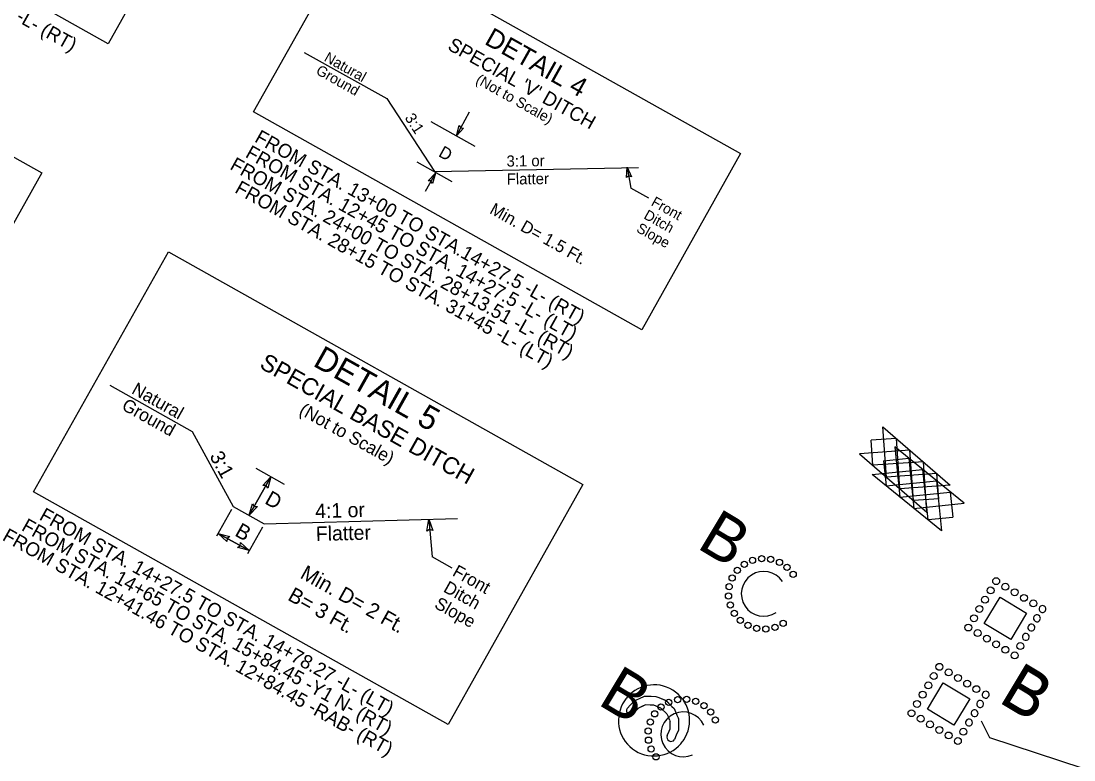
# Model space of a CAD drawing. Extents: x 2283629 to 2286552, y 529718 to 531440.
# Drawn here: x 2284293.2 to 2284634, y 530837.2 to 531076.3 of the extents above; entities that cross this region are included whole.
import ezdxf

# ---------------------------------------------------------------- set-up
doc = ezdxf.new("R2010")
doc.units = 0
for name, color, linetype in [('Draft_Corridor_Graphics_Design', 7, 'Continuous'), ('Draft_RDY_Construction_Class_Element', 7, 'Continuous'), ('P_NCDOT_Terrain_Breakline', 7, 'Continuous'), ('P_NCDOT_Terrain_Hole', 7, 'Continuous'), ('P_NCDOT_Terrain_Island', 7, 'Continuous'), ('P_NCDOT_Terrain_Model_Contour_Major', 7, 'Continuous'), ('P_NCDOT_Terrain_Points_Random', 7, 'Continuous'), ('P_NCDOT_Terrain_Void', 7, 'Continuous'), ('P_RDY_Slope_Stake_Fill_Limits', 7, 'Continuous'), ('P_RDY_TC_Pvmt_Asphalt_Intermediate_Course', 7, 'Continuous'), ('P_RDY_TC_Pvmt_Asphalt_Surface_Course_Wedge', 7, 'Continuous'), ('P_RDY_TL_Sidewalk', 7, 'Continuous'), ('P_RDY_XS_Guardrail_Warrant_Red_Flag', 7, 'Continuous')]:
    doc.layers.add(name, color=color, linetype=linetype)

msp = doc.modelspace()

# ---------------------------------------------------------------- linework, layer by layer
at = {"layer": 'P_NCDOT_Terrain_Breakline'}
for p, q in [((2284434.08, 531039.24), (2284438.39, 531046.91)), ((2284425.82, 531043.87), (2284440.04, 531035.89)), ((2284421.25, 531030.76), (2284432.57, 531024.41)), ((2284427.29, 531027.13), (2284423.95, 531021.17)), ((2284489.42, 531029.06), (2284490.59, 531022.26)), ((2284496.39, 531019), (2284490.59, 531022.26))]:
    msp.add_line(p, q, dxfattribs=at)
for points in [[(2284400.44, 531103.96), (2284526.11, 531033.42), (2284494.1, 530976.4), (2284368.43, 531046.94), (2284400.44, 531103.96)], [(2284174.2, 531097.74), (2284299.87, 531027.2), (2284267.86, 530970.18), (2284142.19, 531040.72), (2284174.2, 531097.74)], [(2284384.79, 531066.21), (2284411.63, 531051.24), (2284427.03, 531027.63), (2284493.01, 531028.95)]]:
    msp.add_lwpolyline(points, dxfattribs=at)
for points in [[(2284436.42, 531041.72), (2284434.08, 531039.24), (2284434.98, 531042.55), (2284435.51, 531041.77)], [(2284424.96, 531024.64), (2284427.29, 531027.13), (2284426.4, 531023.81), (2284425.87, 531024.6)], [(2284489.17, 531025.66), (2284489.42, 531029.06), (2284490.82, 531025.92), (2284489.91, 531026.2)]]:
    msp.add_lwpolyline(points, close=True, dxfattribs=at)
at = {"layer": 'P_NCDOT_Terrain_Hole'}
msp.add_lwpolyline([(2284239.67, 531190.94), (2284353.84, 531126.86), (2284321.37, 531069.02), (2284207.2, 531133.1), (2284239.67, 531190.94)], dxfattribs=at)
at = {"layer": 'P_NCDOT_Terrain_Island'}
for p, q in [((2284369.14, 530931.63), (2284378.33, 530926.5)), ((2284374.08, 530928.86), (2284367.07, 530916.37)), ((2284367.07, 530916.37), (2284374.08, 530928.86)), ((2284361.31, 530918.2), (2284356.47, 530909.58)), ((2284425.14, 530915.08), (2284426.21, 530902.9)), ((2284371.34, 530912.57), (2284366.5, 530903.95)), ((2284357.02, 530910.51), (2284366.97, 530904.93)), ((2284366.97, 530904.93), (2284357.02, 530910.51)), ((2284432.75, 530899.23), (2284426.21, 530902.9))]:
    msp.add_line(p, q, dxfattribs=at)
for points in [[(2284340.88, 531001.69), (2284475.06, 530926.37), (2284431.44, 530848.66), (2284297.25, 530923.98), (2284340.88, 531001.69)], [(2284321.95, 530958.44), (2284348.55, 530943.51), (2284361.82, 530919.22), (2284371.91, 530913.56), (2284434.49, 530915.34)]]:
    msp.add_lwpolyline(points, dxfattribs=at)
for points in [[(2284371.46, 530926.06), (2284374.08, 530928.86), (2284373.08, 530925.12), (2284372.48, 530926)], [(2284369.7, 530919.17), (2284367.07, 530916.37), (2284368.08, 530920.1), (2284368.67, 530919.22)], [(2284424.55, 530911.29), (2284425.14, 530915.08), (2284426.42, 530911.43), (2284425.43, 530911.82)], [(2284359.81, 530907.88), (2284357.02, 530910.51), (2284360.75, 530909.51), (2284359.87, 530908.91)], [(2284364.17, 530907.55), (2284366.97, 530904.93), (2284363.23, 530905.93), (2284364.11, 530906.53)]]:
    msp.add_lwpolyline(points, close=True, dxfattribs=at)
at = {"layer": 'P_NCDOT_Terrain_Model_Contour_Major'}
for p, q in [((2284492.8, 530853.76), (2284491.51, 530852.43)), ((2284492.81, 530853.76), (2284491.52, 530852.42)), ((2284492.8, 530853.76), (2284493.04, 530854)), ((2284492.81, 530853.76), (2284493.05, 530853.99)), ((2284494.39, 530854.6), (2284493.04, 530854)), ((2284494.4, 530854.59), (2284493.05, 530853.99)), ((2284495.33, 530855.01), (2284494.39, 530854.6)), ((2284495.34, 530855), (2284494.4, 530854.59)), ((2284496.78, 530854.97), (2284495.33, 530855.01)), ((2284496.79, 530854.96), (2284495.34, 530855)), ((2284497.98, 530854.93), (2284496.78, 530854.97)), ((2284497.99, 530854.93), (2284496.79, 530854.96)), ((2284500.3, 530853.91), (2284497.98, 530854.93)), ((2284500.31, 530853.9), (2284497.99, 530854.93)), ((2284500.3, 530853.91), (2284500.31, 530853.9)), ((2284500.31, 530853.9), (2284500.32, 530853.9)), ((2284502.22, 530852.09), (2284500.31, 530853.9)), ((2284502.23, 530852.08), (2284500.32, 530853.9)), ((2284502.22, 530852.09), (2284502.72, 530851.01)), ((2284502.23, 530852.08), (2284502.73, 530851)), ((2284503.18, 530850), (2284502.72, 530851.01)), ((2284503.19, 530849.99), (2284502.73, 530851)), ((2284503.18, 530850), (2284503.28, 530849.78)), ((2284503.19, 530849.99), (2284503.29, 530849.78)), ((2284502.35, 530845.08), (2284502.97, 530846.5)), ((2284502.36, 530845.07), (2284502.98, 530846.49)), ((2284502.97, 530846.5), (2284503.28, 530847.23)), ((2284502.98, 530846.49), (2284503.29, 530847.22)), ((2284503.28, 530848.33), (2284503.28, 530849.78)), ((2284503.28, 530847.23), (2284503.28, 530848.33)), ((2284503.29, 530848.33), (2284503.29, 530849.78)), ((2284503.29, 530847.22), (2284503.29, 530848.33))]:
    msp.add_line(p, q, dxfattribs=at)
for points in [[(2284489.34, 530853.86), (2284490.41, 530854.99), (2284491.66, 530856.31), (2284492.42, 530856.65), (2284493.35, 530857.06), (2284494.99, 530857.79), (2284495.03, 530857.79), (2284495.47, 530857.79), (2284495.54, 530857.79), (2284496.5, 530857.79), (2284497.17, 530857.78), (2284498.63, 530857.77), (2284499.59, 530857.37), (2284501.94, 530856.39), (2284501.95, 530856.38), (2284503.84, 530854.54), (2284504.58, 530853.82), (2284505.02, 530852.78), (2284505.11, 530852.56), (2284505.49, 530851.68), (2284505.77, 530851), (2284505.84, 530850.84), (2284505.98, 530850.51), (2284505.99, 530850.5), (2284505.97, 530848.99), (2284505.95, 530847.65), (2284505.94, 530846.84), (2284505.27, 530845.21), (2284504.68, 530843.78)], [(2284489.35, 530853.85), (2284490.42, 530854.99), (2284491.67, 530856.31), (2284492.43, 530856.65), (2284493.36, 530857.06), (2284495, 530857.79), (2284495.04, 530857.79), (2284495.48, 530857.78), (2284495.55, 530857.79), (2284496.51, 530857.78), (2284497.17, 530857.78), (2284498.64, 530857.77), (2284499.6, 530857.37), (2284501.95, 530856.38), (2284501.96, 530856.37), (2284503.85, 530854.53), (2284504.59, 530853.81), (2284505.03, 530852.77), (2284505.12, 530852.55), (2284505.5, 530851.67), (2284505.78, 530851), (2284505.85, 530850.84), (2284505.99, 530850.5), (2284506, 530850.49), (2284505.98, 530848.98), (2284505.96, 530847.64), (2284505.95, 530846.83), (2284505.28, 530845.21), (2284504.69, 530843.78)]]:
    msp.add_lwpolyline(points, dxfattribs=at)
for centre, radius, start, end in [((2284498.09, 530850.01), 11.5, 326.5279, 139.1744), ((2284498.06, 530849.97), 11.5, 138.9333, 146.5279), ((2284498.06, 530849.97), 11.5, 146.5279, 318.9333), ((2284490.42, 530853.15), 1.3, 146.5279, 326.5279), ((2284490.43, 530853.14), 1.3, 146.5279, 326.5279), ((2284503.57, 530844.52), 1.33, 155.4153, 326.5279), ((2284503.57, 530844.51), 1.33, 155.4153, 326.5279), ((2284498.09, 530850.01), 11.5, 318.6921, 326.5279)]:
    msp.add_arc(centre, radius, start, end, dxfattribs=at)
at = {"layer": 'P_NCDOT_Terrain_Points_Random'}
msp.add_lwpolyline([(2284603.92, 530849.87), (2284606.71, 530844.47), (2284636.9, 530834.54), (2284715.51, 530802.89), (2284733.68, 530793.16), (2284744.13, 530816.82)], dxfattribs=at)
at = {"layer": 'P_NCDOT_Terrain_Void'}
for p, q in [((2284576.02, 530938.52), (2284577.69, 530922.27)), ((2284598.44, 530920.29), (2284576.02, 530938.52)), ((2284572.35, 530934.03), (2284580.52, 530934.86)), ((2284572.35, 530934.03), (2284573.22, 530925.89)), ((2284580.52, 530934.86), (2284582.19, 530918.61)), ((2284568.73, 530929.56), (2284584.98, 530931.23)), ((2284591.15, 530911.33), (2284568.73, 530929.56)), ((2284584.98, 530931.23), (2284586.69, 530914.95)), ((2284573.22, 530925.89), (2284589.48, 530927.57)), ((2284589.48, 530927.57), (2284591.15, 530911.33)), ((2284577.69, 530922.27), (2284593.98, 530923.91)), ((2284593.98, 530923.91), (2284594.79, 530915.78)), ((2284582.19, 530918.61), (2284598.44, 530920.29)), ((2284586.76, 530914.96), (2284594.79, 530915.78))]:
    msp.add_line(p, q, dxfattribs=at)
at = {"layer": 'P_RDY_Slope_Stake_Fill_Limits'}
for p, q in [((2284624.75, 530885.42), (2284624.81, 530885.51)), ((2284622.95, 530882.42), (2284623, 530882.51)), ((2284621.15, 530879.43), (2284621.2, 530879.5)), ((2284619.36, 530876.43), (2284619.39, 530876.49))]:
    msp.add_line(p, q, dxfattribs=at)
msp.add_lwpolyline([(2284610.1, 530889.89), (2284618.67, 530884.74), (2284613.52, 530876.17), (2284604.96, 530881.33)], close=True, dxfattribs=at)
for centre in [(2284608.82, 530895.06), (2284611.82, 530893.25), (2284607.02, 530892.05), (2284614.82, 530891.45), (2284617.82, 530889.65), (2284605.21, 530889.05), (2284620.82, 530887.85), (2284601.61, 530883.05), (2284603.41, 530886.05), (2284599.81, 530880.05), (2284602.81, 530878.25), (2284605.81, 530876.45), (2284608.81, 530874.65), (2284611.81, 530872.84), (2284616.61, 530874.04), (2284614.81, 530871.04)]:
    msp.add_circle(centre, 1.12, dxfattribs=at)
for centre, start, end in [((2284622.02, 530883.04), 331.5202, 326.4973), ((2284623.82, 530886.04), 331.8167, 326.2009), ((2284620.21, 530880.04), 331.1837, 326.8339), ((2284618.41, 530877.04), 330.7846, 327.233)]:
    msp.add_arc(centre, 1.12, start, end, dxfattribs=at)
at = {"layer": 'P_RDY_TC_Pvmt_Asphalt_Intermediate_Course'}
for p, q in [((2284606.36, 530857.68), (2284606.42, 530857.78)), ((2284604.57, 530854.69), (2284604.62, 530854.77)), ((2284602.77, 530851.69), (2284602.81, 530851.77)), ((2284600.97, 530848.7), (2284601, 530848.76))]:
    msp.add_line(p, q, dxfattribs=at)
msp.add_lwpolyline([(2284591.71, 530862.15), (2284600.28, 530857.01), (2284595.13, 530848.43), (2284586.57, 530853.59)], close=True, dxfattribs=at)
for centre in [(2284590.43, 530867.32), (2284588.63, 530864.32), (2284593.43, 530865.52), (2284596.43, 530863.72), (2284586.83, 530861.32), (2284599.43, 530861.91), (2284602.43, 530860.11), (2284585.02, 530858.32), (2284581.42, 530852.32), (2284583.22, 530855.32), (2284584.42, 530850.52), (2284587.42, 530848.71), (2284590.42, 530846.91), (2284598.22, 530846.31), (2284593.42, 530845.11), (2284596.42, 530843.31)]:
    msp.add_circle(centre, 1.12, dxfattribs=at)
for centre, start, end in [((2284605.43, 530858.31), 331.8167, 326.2009), ((2284601.83, 530852.31), 331.1837, 326.8339), ((2284603.63, 530855.31), 331.5202, 326.4973), ((2284600.02, 530849.31), 330.7846, 327.233)]:
    msp.add_arc(centre, 1.12, start, end, dxfattribs=at)
at = {"layer": 'P_RDY_TC_Pvmt_Asphalt_Surface_Course_Wedge'}
for centre in [(2284502.84, 530855.86), (2284505.69, 530856.72), (2284508.67, 530856.82), (2284511.58, 530856.14), (2284500.3, 530854.29), (2284514.21, 530854.73), (2284516.38, 530852.69), (2284496.85, 530849.49), (2284498.26, 530852.11), (2284517.95, 530850.15), (2284496.17, 530846.58), (2284496.27, 530843.6), (2284497.13, 530840.75), (2284498.7, 530838.21)]:
    msp.add_circle(centre, 1.01, dxfattribs=at)
msp.add_arc((2284507.54, 530845.45), 7.26, 24.311, 294.3022, dxfattribs=at)
at = {"layer": 'P_RDY_TL_Sidewalk'}
for p, q in [((2284572.17, 530945.04), (2284593.98, 530926.08)), ((2284573.31, 530928.74), (2284572.17, 530945.04)), ((2284576.44, 530941.26), (2284568.39, 530940.7)), ((2284568.93, 530932.55), (2284568.39, 530940.7)), ((2284577.69, 530924.94), (2284576.51, 530941.26)), ((2284580.89, 530937.46), (2284564.6, 530936.32)), ((2284564.6, 530936.32), (2284586.41, 530917.36)), ((2284582.03, 530921.16), (2284580.89, 530937.46)), ((2284585.27, 530933.65), (2284568.93, 530932.55)), ((2284586.41, 530917.36), (2284585.27, 530933.65)), ((2284589.62, 530929.89), (2284573.31, 530928.74)), ((2284590.22, 530921.73), (2284589.62, 530929.89)), ((2284593.98, 530926.08), (2284577.69, 530924.94)), ((2284590.22, 530921.73), (2284582.03, 530921.16))]:
    msp.add_line(p, q, dxfattribs=at)
at = {"layer": 'P_RDY_XS_Guardrail_Warrant_Red_Flag'}
for centre in [(2284527.28, 530900.49), (2284529.96, 530901.79), (2284532.89, 530902.36), (2284535.86, 530902.15), (2284538.68, 530901.18), (2284525.03, 530898.53), (2284541.15, 530899.51), (2284543.11, 530897.26), (2284522.38, 530893.24), (2284523.36, 530896.06), (2284522.17, 530890.27), (2284522.74, 530887.34), (2284524.05, 530884.66), (2284526, 530882.41), (2284528.47, 530880.74), (2284531.29, 530879.76), (2284534.27, 530879.55), (2284537.2, 530880.12), (2284539.88, 530881.43)]:
    msp.add_circle(centre, 1.01, dxfattribs=at)
msp.add_arc((2284533.58, 530890.96), 7.26, 33.4702, 303.4614, dxfattribs=at)

# ---------------------------------------------------------------- texts
at = {"layer": 'Draft_Corridor_Graphics_Design'}
for p in [(2284479.49, 530855.39), (2284609.43, 530856.35)]:
    msp.add_text('B', height=15, rotation=329.0088, dxfattribs=at).set_placement(p)
at = {"layer": 'Draft_RDY_Construction_Class_Element'}
for p in [(2284511.53, 530906), (2284609.21, 530856.12)]:
    msp.add_text('B', height=15, rotation=329.0088, dxfattribs=at).set_placement(p)
at = {"layer": 'P_NCDOT_Terrain_Breakline'}
for s, height, rotation, p in [('DETAIL 4', 6.187, 330.6931, (2284442.87, 531069.07)), ("SPECIAL 'V' DITCH", 4.4997, 330.6931, (2284430.92, 531067.31)), ('Natural', 3.375, 330.6931, (2284391.01, 531063.58)), ('Ground', 3.375, 330.6931, (2284388.36, 531059.39)), ('(Not to Scale)', 3.375, 330.6931, (2284440.06, 531056.42)), ('3:1', 3.6, 302.9443, (2284417.23, 531045.05)), ('FROM STA. 13+00 TO STA.14+27.5 -L- (RT)', 4.5, 330.6931, (2284368.48, 531037.45)), ('FROM STA. 12+45 TO STA. 14+27.5 -L- (LT)', 4.5, 330.6931, (2284365.48, 531032.46)), ('D', 3.94, 330.6931, (2284428.02, 531032.73)), ('FROM STA. 24+00 TO STA. 28+13.51 -L- (RT)', 4.5, 330.6931, (2284360.49, 531028.58)), ('3:1 or', 3.6, 0.6931, (2284450.35, 531029.22)), ('Flatter', 3.6, 0.6931, (2284450.42, 531023.4)), ('FROM STA. 28+15 TO STA. 31+45 -L- (LT)', 4.5, 330.6931, (2284362.06, 531021.02)), ('Min. D= 1.5 Ft.', 3.9374, 330.6931, (2284444.55, 531014.28)), ('Front', 3.33, 330.6931, (2284496.87, 531016.83)), ('Ditch', 3.33, 330.6931, (2284494.48, 531012.57)), ('Slope', 3.33, 330.6931, (2284492.09, 531008.31))]:
    msp.add_text(s, height=height, rotation=rotation, dxfattribs=at).set_placement(p)
at = {"layer": 'P_NCDOT_Terrain_Hole'}
msp.add_text('FROM STA. 27+51.5 TO STA. 28+10 -L- (RT)', height=4.5, rotation=330.6931, dxfattribs=at).set_placement((2284202.59, 531126.34))
at = {"layer": 'P_NCDOT_Terrain_Island'}
for s, height, rotation, p in [('DETAIL 5', 7.618, 330.6931, (2284387.34, 530964.91)), ('SPECIAL BASE DITCH', 5.5402, 330.6931, (2284370.02, 530964.25)), ('Natural', 4.155, 330.6931, (2284328.66, 530955.99)), ('Ground', 4.155, 330.6931, (2284325.44, 530950.81)), ('(Not to Scale)', 4.1555, 330.6931, (2284382.87, 530949.31)), ('3:1', 4.691, 298.6525, (2284354.07, 530935.55)), ('D', 4.85, 330.6931, (2284371.73, 530920.36)), ('FROM STA. 14+27.5 TO STA. 14+78.27 -L- (LT)', 4.5, 330.6931, (2284298.77, 530915.14)), ('4:1 or', 4.702, 1.6267, (2284388.45, 530915.41)), ('FROM STA. 14+65 TO STA. 15+84.45 -Y1 N- (RT)', 4.5, 330.6931, (2284293.03, 530911.69)), ('FROM STA. 12+41.46 TO STA. 12+84.45 -RAB- (RT)', 4.5, 330.6931, (2284286.82, 530908.49)), ('B', 4.85, 330.6931, (2284362.05, 530909.94)), ('Flatter', 4.702, 1.6267, (2284388.66, 530908.02)), ('Min. D= 2 Ft.', 4.8479, 330.6931, (2284383.19, 530896.25)), ('Front', 4.074, 330.6931, (2284432.52, 530897.02)), ('Ditch', 4.074, 330.6931, (2284429.59, 530891.81)), ('B= 3 Ft.', 4.848, 330.6931, (2284379.19, 530889.13)), ('Slope', 4.074, 330.6931, (2284426.67, 530886.6))]:
    msp.add_text(s, height=height, rotation=rotation, dxfattribs=at).set_placement(p)

doc.saveas('drawing.dxf')
